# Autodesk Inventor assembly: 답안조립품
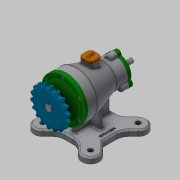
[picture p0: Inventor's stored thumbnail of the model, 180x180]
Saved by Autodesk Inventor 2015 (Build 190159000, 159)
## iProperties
Created: 2018-03
Part Number: 답안조립품
Document SubType Name: Assembly
Designer: SCD-A011
Author: SCD-A011
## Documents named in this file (15)
- C:\Users\SCD-A011\Desktop\480308V1005\답안조립품.iam
- C:\Users\SCD-A011\Desktop\480308V1005\뒤커버.ipt
- C:\Users\SCD-A011\Desktop\480308V1005\마개.ipt
- C:\Users\SCD-A011\Desktop\480308V1005\베어링-6200.ipt
- C:\Users\SCD-A011\Desktop\480308V1005\베어링-6203.ipt
- C:\Users\SCD-A011\Desktop\480308V1005\본체.ipt
- C:\Users\SCD-A011\Desktop\480308V1005\볼트 M4 x 12.ipt
- 볼트 M4 x 12.ipt
- C:\Users\SCD-A011\Desktop\480308V1005\스프로킷.ipt
- C:\Users\SCD-A011\Desktop\480308V1005\앞커버.ipt
- C:\Users\SCD-A011\Desktop\480308V1005\오일 실 10 20 7.ipt
- C:\Users\SCD-A011\Desktop\480308V1005\오일 실 17 30 8.ipt
- C:\Users\SCD-A011\Desktop\480308V1005\축.ipt
- C:\Users\SCD-A011\Desktop\480308V1005\키 5 x 5.ipt
- 키 5 x 5.ipt
